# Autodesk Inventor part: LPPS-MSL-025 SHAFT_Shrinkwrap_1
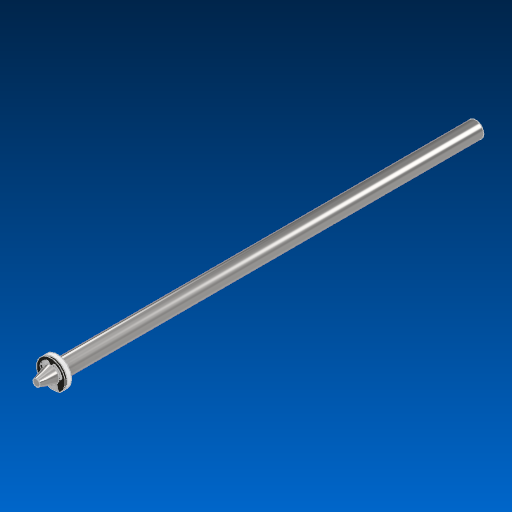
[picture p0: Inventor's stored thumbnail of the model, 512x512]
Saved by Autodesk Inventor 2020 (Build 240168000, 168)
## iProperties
Created: 2019-07
Part Number: LPPS-MSL-025 SHAFT_Shrinkwrap_1
Material: Generic
Document SubType Name: Modeling
Designer: J. Nielson
Density: 1 g/cm^3
Appearance: Default
Author: J. Nielson
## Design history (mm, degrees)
node "Assembly1" dims "d0" = 10
body "Solid1"
node "Part1:1" dims "d0" = 10
node "Part2:1" dims "d0" = 10
body "Solid2"
node "Part3:1" dims "d0" = 10
body "Solid3"
